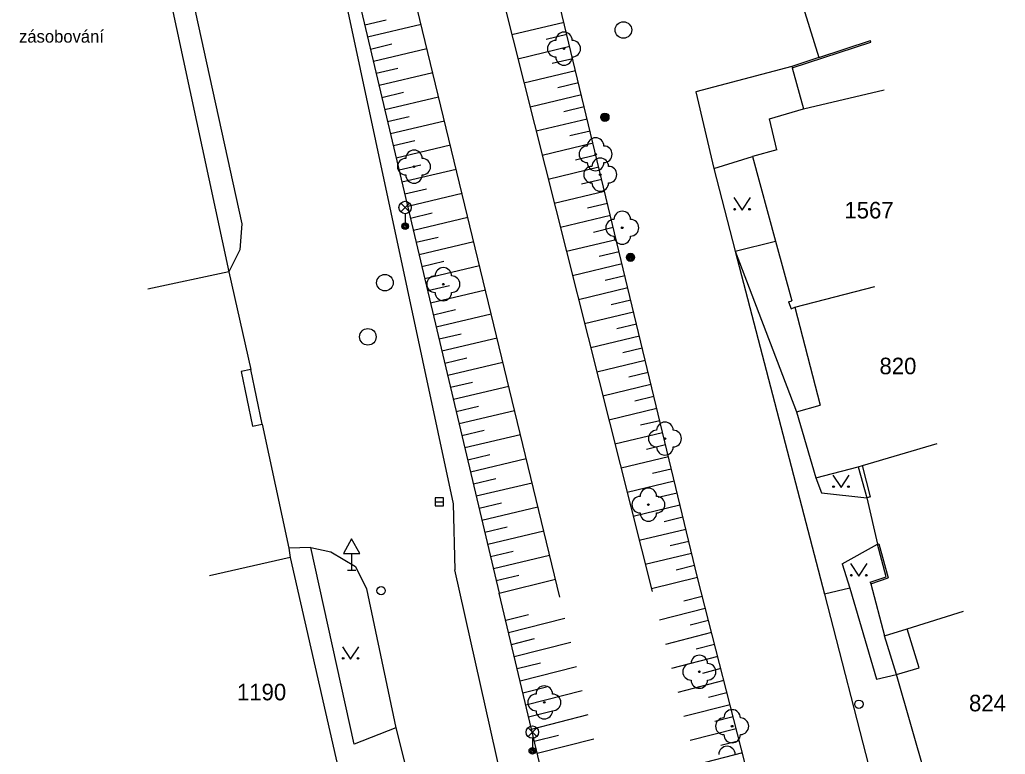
# Model space of a CAD drawing. Extents: x -539515 to -538098, y -1182060 to -1180157.
# Drawn here: x -539059.5 to -538999.9, y -1180485.6 to -1180441.2 of the extents above; entities that cross this region are included whole.
import ezdxf

# ---------------------------------------------------------------- set-up
doc = ezdxf.new("R2010")
doc.units = 0
for name, color, linetype in [('Vrstva 1', 7, 'Continuous'), ('Vrstva 11', 7, 'Continuous'), ('Vrstva 13', 7, 'Continuous'), ('Vrstva 22', 7, 'Continuous'), ('Vrstva 25', 7, 'Continuous'), ('Vrstva 27', 7, 'Continuous'), ('Vrstva 28', 7, 'Continuous'), ('Vrstva 29', 7, 'Continuous'), ('Vrstva 33', 7, 'Continuous'), ('Vrstva 34', 7, 'Continuous'), ('Vrstva 36', 7, 'Continuous'), ('Vrstva 41', 7, 'Continuous'), ('Vrstva 47', 7, 'Continuous'), ('Vrstva 68', 7, 'Continuous'), ('Vrstva 88', 7, 'Continuous')]:
    doc.layers.add(name, color=color, linetype=linetype)

msp = doc.modelspace()

# ---------------------------------------------------------------- linework, layer by layer
at = {"layer": 'Vrstva 1'}
for p, q in [((-539054.01, -1180422.97), (-539046.82, -1180456.41)), ((-539012.1, -1180446.56), (-539007.231, -1180445.422)), ((-539014.15, -1180447.16), (-539012.1, -1180446.56)), ((-539013.71, -1180449.05), (-539014.15, -1180447.16)), ((-539013.71, -1180449.05), (-539015.17, -1180449.45)), ((-539015.17, -1180449.45), (-539013.78, -1180454.57)), ((-539013.78, -1180454.57), (-539012.806, -1180458.156)), ((-539046.82, -1180456.41), (-539051.708, -1180457.461)), ((-539012.628, -1180458.547), (-539007.787, -1180457.297)), ((-539013, -1180458.219), (-539012.806, -1180458.156)), ((-539013, -1180458.219), (-539012.84, -1180458.641)), ((-539012.84, -1180458.641), (-539012.628, -1180458.547)), ((-539012.628, -1180458.547), (-539011.1, -1180464.461)), ((-539012.53, -1180464.87), (-539011.1, -1180464.461)), ((-539012.53, -1180464.87), (-539011.36, -1180468.859)), ((-539008.53, -1180468.108), (-539004.03, -1180466.781)), ((-539011.36, -1180468.859), (-539008.8, -1180468.19)), ((-539008.8, -1180468.19), (-539008.53, -1180468.108)), ((-539043.11, -1180473.68), (-539047.988, -1180474.773)), ((-539043.11, -1180473.68), (-539039.78, -1180488.31)), ((-539005.837, -1180477.983), (-539002.425, -1180476.922)), ((-539007.2, -1180478.41), (-539005.837, -1180477.983)), ((-539006.48, -1180480.75), (-539007.2, -1180478.41)), ((-539005.103, -1180480.344), (-539005.837, -1180477.983)), ((-539006.48, -1180480.75), (-539005.103, -1180480.344)), ((-539004.67, -1180487.07), (-539006.48, -1180480.75))]:
    msp.add_line(p, q, dxfattribs=at)
at = {"layer": 'Vrstva 11'}
for p, q in [((-539012.32, -1180439.742), (-539011.18, -1180443.461)), ((-539008.28, -1180470.07), (-539007.62, -1180472.87))]:
    msp.add_line(p, q, dxfattribs=at)
for points in [[(-539012.8, -1180444), (-539012.776, -1180444.087), (-539012.1, -1180446.56)], [(-539008.06, -1180475.17), (-539008.034, -1180475.269), (-539007.2, -1180478.41)]]:
    msp.add_lwpolyline(points, dxfattribs=at)
at = {"layer": 'Vrstva 13'}
for p, q in [((-539017.52, -1180450.16), (-539015.17, -1180449.45)), ((-539016.23, -1180455.17), (-539013.78, -1180454.57)), ((-539016.23, -1180455.17), (-539012.53, -1180464.87)), ((-539011.36, -1180468.859), (-539011.02, -1180469.77)), ((-539011.02, -1180469.77), (-539008.28, -1180470.07)), ((-539039.24, -1180484.95), (-539041.87, -1180473.08)), ((-539009.76, -1180474.06), (-539007.62, -1180472.87)), ((-539009.76, -1180474.06), (-539009.29, -1180475.53)), ((-539009.29, -1180475.53), (-539010.82, -1180475.89)), ((-539009.29, -1180475.53), (-539007.69, -1180481.03)), ((-539007.69, -1180481.03), (-539006.48, -1180480.75)), ((-539036.73, -1180483.96), (-539039.24, -1180484.95))]:
    msp.add_line(p, q, dxfattribs=at)
at = {"layer": 'Vrstva 22'}
for centre in [(-539026.57, -1180442.93), (-539024.66, -1180449.31), (-539035.63, -1180450.06), (-539024.38, -1180450.539), (-539023.05, -1180453.75), (-539033.86, -1180457.16), (-539020.47, -1180466.49), (-539021.47, -1180470.48), (-539018.39, -1180480.58), (-539027.76, -1180482.43), (-539016.41, -1180483.87)]:
    msp.add_circle(centre, 0.05, dxfattribs=at)
for centre, start, end in [((-539026.57, -1180442.43), 0, 180), ((-539027.07, -1180442.93), 90, 270), ((-539026.07, -1180442.93), 270, 90), ((-539026.57, -1180443.43), 180, 0), ((-539024.66, -1180448.81), 0, 180), ((-539035.63, -1180449.56), 0, 180), ((-539025.16, -1180449.31), 90, 270), ((-539024.16, -1180449.31), 270, 90), ((-539036.13, -1180450.06), 90, 270), ((-539035.13, -1180450.06), 270, 90), ((-539024.66, -1180449.81), 180, 0), ((-539024.38, -1180450.039), 0, 180), ((-539024.88, -1180450.539), 90, 270), ((-539023.88, -1180450.539), 270, 90), ((-539035.63, -1180450.56), 180, 0), ((-539024.38, -1180451.039), 180, 0), ((-539023.05, -1180453.25), 0, 180), ((-539023.55, -1180453.75), 90, 270), ((-539022.55, -1180453.75), 270, 90), ((-539023.05, -1180454.25), 180, 0), ((-539033.86, -1180456.66), 0, 180), ((-539034.36, -1180457.16), 90, 270), ((-539033.36, -1180457.16), 270, 90), ((-539033.86, -1180457.66), 180, 0), ((-539020.97, -1180466.49), 90, 270), ((-539020.47, -1180465.99), 0, 180), ((-539019.97, -1180466.49), 270, 90), ((-539020.47, -1180466.99), 180, 0), ((-539021.47, -1180469.98), 0, 180), ((-539021.97, -1180470.48), 90, 270), ((-539020.97, -1180470.48), 270, 90), ((-539021.47, -1180470.98), 180, 0), ((-539018.39, -1180480.08), 0, 180), ((-539018.89, -1180480.58), 90, 270), ((-539017.89, -1180480.58), 270, 90), ((-539027.76, -1180481.93), 0, 180), ((-539018.39, -1180481.08), 180, 0), ((-539028.26, -1180482.43), 90, 270), ((-539027.26, -1180482.43), 270, 90), ((-539027.76, -1180482.93), 180, 0), ((-539016.41, -1180483.37), 0, 180), ((-539016.91, -1180483.87), 90, 270), ((-539015.91, -1180483.87), 270, 90), ((-539016.41, -1180484.37), 180, 0), ((-539016.72, -1180485.58), 0, 180)]:
    msp.add_arc(centre, 0.5, start, end, dxfattribs=at)
at = {"layer": 'Vrstva 25'}
for centre, radius in [((-539024.1, -1180447.07), 0.25), ((-539024.1, -1180447.07), 0.2), ((-539024.1, -1180447.07), 0.15), ((-539024.1, -1180447.07), 0.1), ((-539024.1, -1180447.07), 0.05), ((-539022.55, -1180455.539), 0.25), ((-539022.55, -1180455.539), 0.2), ((-539022.55, -1180455.539), 0.15), ((-539022.55, -1180455.539), 0.1), ((-539022.55, -1180455.539), 0.05)]:
    msp.add_circle(centre, radius, dxfattribs=at)
at = {"layer": 'Vrstva 27'}
for p, q in [((-539038.606, -1180441.491), (-539037.314, -1180441.185)), ((-539038.433, -1180442.22), (-539035.201, -1180441.456)), ((-539026.568, -1180441.345), (-539029.719, -1180442.102)), ((-539026.392, -1180442.074), (-539027.65, -1180442.376)), ((-539038.26, -1180442.95), (-539036.966, -1180442.644)), ((-539038.087, -1180443.68), (-539034.848, -1180442.913)), ((-539026.217, -1180442.804), (-539029.352, -1180443.557)), ((-539026.042, -1180443.533), (-539027.293, -1180443.833)), ((-539037.915, -1180444.41), (-539036.617, -1180444.103)), ((-539037.742, -1180445.14), (-539034.495, -1180444.372)), ((-539025.867, -1180444.262), (-539028.986, -1180445.012)), ((-539025.692, -1180444.991), (-539026.936, -1180445.29)), ((-539037.569, -1180445.87), (-539036.269, -1180445.562)), ((-539025.517, -1180445.721), (-539028.62, -1180446.466)), ((-539037.397, -1180446.599), (-539034.142, -1180445.829)), ((-539025.341, -1180446.45), (-539026.579, -1180446.747)), ((-539037.224, -1180447.329), (-539035.92, -1180447.021)), ((-539037.051, -1180448.059), (-539033.789, -1180447.287)), ((-539025.166, -1180447.179), (-539028.253, -1180447.921)), ((-539024.991, -1180447.908), (-539026.223, -1180448.204)), ((-539036.879, -1180448.789), (-539035.572, -1180448.48)), ((-539036.706, -1180449.519), (-539033.436, -1180448.745)), ((-539024.816, -1180448.638), (-539027.887, -1180449.375)), ((-539036.533, -1180450.249), (-539035.224, -1180449.939)), ((-539024.641, -1180449.367), (-539025.866, -1180449.661)), ((-539036.36, -1180450.979), (-539033.083, -1180450.203)), ((-539024.466, -1180450.096), (-539027.52, -1180450.83)), ((-539024.29, -1180450.825), (-539025.509, -1180451.118)), ((-539036.188, -1180451.708), (-539034.875, -1180451.398)), ((-539036.015, -1180452.438), (-539032.73, -1180451.661)), ((-539024.115, -1180451.555), (-539027.154, -1180452.284)), ((-539023.94, -1180452.284), (-539025.152, -1180452.575)), ((-539035.842, -1180453.168), (-539034.527, -1180452.857)), ((-539035.67, -1180453.898), (-539032.377, -1180453.119)), ((-539023.765, -1180453.013), (-539026.787, -1180453.739)), ((-539023.59, -1180453.743), (-539024.795, -1180454.032)), ((-539035.497, -1180454.628), (-539034.178, -1180454.316)), ((-539035.324, -1180455.358), (-539032.024, -1180454.577)), ((-539023.415, -1180454.472), (-539026.421, -1180455.194)), ((-539023.239, -1180455.201), (-539024.439, -1180455.489)), ((-539035.151, -1180456.087), (-539033.83, -1180455.775)), ((-539034.979, -1180456.817), (-539031.671, -1180456.035)), ((-539023.064, -1180455.93), (-539026.054, -1180456.649)), ((-539022.889, -1180456.66), (-539024.082, -1180456.946)), ((-539034.806, -1180457.547), (-539033.481, -1180457.234)), ((-539034.633, -1180458.277), (-539031.318, -1180457.492)), ((-539022.714, -1180457.389), (-539025.688, -1180458.103)), ((-539022.539, -1180458.118), (-539023.725, -1180458.403)), ((-539034.461, -1180459.007), (-539033.133, -1180458.693)), ((-539022.364, -1180458.847), (-539025.321, -1180459.558)), ((-539034.288, -1180459.737), (-539030.965, -1180458.95)), ((-539022.188, -1180459.577), (-539023.368, -1180459.86)), ((-539034.115, -1180460.467), (-539032.784, -1180460.152)), ((-539033.942, -1180461.196), (-539030.612, -1180460.408)), ((-539022.013, -1180460.306), (-539024.955, -1180461.012)), ((-539021.838, -1180461.035), (-539023.012, -1180461.317)), ((-539033.77, -1180461.926), (-539032.436, -1180461.611)), ((-539021.663, -1180461.764), (-539024.588, -1180462.467)), ((-539033.597, -1180462.656), (-539030.259, -1180461.866)), ((-539021.488, -1180462.494), (-539022.655, -1180462.774)), ((-539033.424, -1180463.386), (-539032.088, -1180463.07)), ((-539033.252, -1180464.116), (-539029.906, -1180463.324)), ((-539021.313, -1180463.223), (-539024.222, -1180463.921)), ((-539021.137, -1180463.952), (-539022.298, -1180464.231)), ((-539033.079, -1180464.846), (-539031.739, -1180464.528)), ((-539032.906, -1180465.575), (-539029.553, -1180464.782)), ((-539020.962, -1180464.681), (-539023.856, -1180465.376)), ((-539020.787, -1180465.411), (-539021.941, -1180465.688)), ((-539032.733, -1180466.305), (-539031.391, -1180465.988)), ((-539032.561, -1180467.035), (-539029.2, -1180466.24)), ((-539020.612, -1180466.14), (-539023.489, -1180466.831)), ((-539020.437, -1180466.869), (-539021.584, -1180467.145)), ((-539032.388, -1180467.765), (-539031.042, -1180467.447)), ((-539032.215, -1180468.495), (-539028.847, -1180467.698)), ((-539020.262, -1180467.598), (-539023.123, -1180468.286)), ((-539020.086, -1180468.328), (-539021.228, -1180468.602)), ((-539032.043, -1180469.225), (-539030.694, -1180468.905)), ((-539031.87, -1180469.954), (-539028.494, -1180469.156)), ((-539019.911, -1180469.057), (-539022.756, -1180469.74)), ((-539019.736, -1180469.786), (-539020.871, -1180470.059)), ((-539034.35, -1180470.31), (-539033.85, -1180470.31)), ((-539031.697, -1180470.684), (-539030.345, -1180470.364)), ((-539031.524, -1180471.414), (-539028.141, -1180470.613)), ((-539019.561, -1180470.515), (-539022.39, -1180471.195)), ((-539019.386, -1180471.245), (-539020.514, -1180471.516)), ((-539031.352, -1180472.144), (-539029.997, -1180471.823)), ((-539019.211, -1180471.974), (-539022.023, -1180472.65)), ((-539031.179, -1180472.874), (-539027.788, -1180472.072)), ((-539019.035, -1180472.703), (-539020.157, -1180472.973)), ((-539031.006, -1180473.604), (-539029.648, -1180473.282)), ((-539030.834, -1180474.334), (-539027.435, -1180473.529)), ((-539018.86, -1180473.432), (-539021.657, -1180474.104)), ((-539018.685, -1180474.162), (-539019.801, -1180474.43)), ((-539030.661, -1180475.063), (-539029.3, -1180474.741)), ((-539018.51, -1180474.891), (-539021.29, -1180475.559)), ((-539030.48, -1180475.83), (-539027.082, -1180474.987)), ((-539018.217, -1180476.031), (-539019.326, -1180476.316)), ((-539030.092, -1180477.47), (-539028.716, -1180477.121)), ((-539029.919, -1180478.2), (-539026.515, -1180477.337)), ((-539018.03, -1180476.757), (-539020.804, -1180477.471)), ((-539017.843, -1180477.484), (-539018.953, -1180477.769)), ((-539017.656, -1180478.21), (-539020.434, -1180478.925)), ((-539029.746, -1180478.929), (-539028.354, -1180478.577)), ((-539029.573, -1180479.659), (-539026.165, -1180478.795)), ((-539017.469, -1180478.936), (-539018.581, -1180479.223)), ((-539017.282, -1180479.663), (-539020.064, -1180480.378)), ((-539029.4, -1180480.389), (-539027.993, -1180480.032)), ((-539029.227, -1180481.119), (-539025.814, -1180480.254)), ((-539017.095, -1180480.389), (-539018.208, -1180480.676)), ((-539029.054, -1180481.849), (-539027.631, -1180481.488)), ((-539016.908, -1180481.115), (-539019.694, -1180481.832)), ((-539028.881, -1180482.579), (-539025.463, -1180481.712)), ((-539016.721, -1180481.842), (-539017.836, -1180482.129)), ((-539016.534, -1180482.568), (-539019.323, -1180483.286)), ((-539028.709, -1180483.309), (-539027.269, -1180482.944)), ((-539028.536, -1180484.039), (-539025.112, -1180483.171)), ((-539016.347, -1180483.294), (-539017.464, -1180483.582)), ((-539028.363, -1180484.769), (-539026.908, -1180484.4)), ((-539016.16, -1180484.021), (-539018.953, -1180484.739)), ((-539028.19, -1180485.499), (-539024.762, -1180484.629)), ((-539015.973, -1180484.747), (-539017.091, -1180485.035)), ((-539015.787, -1180485.473), (-539018.583, -1180486.193))]:
    msp.add_line(p, q, dxfattribs=at)
msp.add_lwpolyline([(-539034.35, -1180470.56), (-539033.85, -1180470.56), (-539033.85, -1180470.06), (-539034.35, -1180470.06)], close=True, dxfattribs=at)
for centre in [(-539022.98, -1180441.8), (-539037.39, -1180457.07), (-539038.42, -1180460.34)]:
    msp.add_circle(centre, 0.5, dxfattribs=at)
at = {"layer": 'Vrstva 28'}
for centre in [(-539037.62, -1180475.68), (-539008.75, -1180482.539)]:
    msp.add_circle(centre, 0.25, dxfattribs=at)
at = {"layer": 'Vrstva 29'}
for p, q in [((-539032.443, -1180431.289), (-539021.25, -1180475.719)), ((-539026.82, -1180476.07), (-539037.301, -1180432.781)), ((-539018.51, -1180474.89), (-539028.45, -1180433.51)), ((-539040.16, -1180434.92), (-539030.48, -1180475.83)), ((-539012.048, -1180500), (-539018.51, -1180474.89)), ((-539026.11, -1180494.28), (-539030.48, -1180475.83))]:
    msp.add_line(p, q, dxfattribs=at)
at = {"layer": 'Vrstva 33'}
for p, q in [((-539036.434, -1180452.791), (-539035.906, -1180452.261)), ((-539036.434, -1180452.261), (-539035.906, -1180452.791)), ((-539036.17, -1180452.9), (-539036.17, -1180453.65)), ((-539028.744, -1180484.491), (-539028.216, -1180483.961)), ((-539028.744, -1180483.961), (-539028.216, -1180484.491)), ((-539028.48, -1180484.6), (-539028.48, -1180485.35))]:
    msp.add_line(p, q, dxfattribs=at)
for centre, radius in [((-539036.17, -1180452.526), 0.375), ((-539036.17, -1180453.651), 0.2), ((-539036.17, -1180453.651), 0.145), ((-539036.17, -1180453.651), 0.0876), ((-539028.48, -1180484.226), 0.375), ((-539028.48, -1180485.351), 0.2), ((-539028.48, -1180485.351), 0.145), ((-539028.48, -1180485.351), 0.0876)]:
    msp.add_circle(centre, radius, dxfattribs=at)
at = {"layer": 'Vrstva 34'}
for p, q in [((-539039.4, -1180473.424), (-539039.4, -1180474.44)), ((-539039.65, -1180474.44), (-539039.15, -1180474.44))]:
    msp.add_line(p, q, dxfattribs=at)
msp.add_lwpolyline([(-539039.9, -1180473.424), (-539038.9, -1180473.424), (-539039.4, -1180472.556)], close=True, dxfattribs=at)
at = {"layer": 'Vrstva 36'}
for points in [[(-539016.308, -1180451.93), (-539015.808, -1180452.68), (-539015.308, -1180451.93)], [(-539010.331, -1180468.695), (-539009.831, -1180469.445), (-539009.331, -1180468.695)], [(-539009.253, -1180474.047), (-539008.753, -1180474.797), (-539008.253, -1180474.047)], [(-539039.962, -1180479.07), (-539039.462, -1180479.82), (-539038.962, -1180479.07)]]:
    msp.add_lwpolyline(points, dxfattribs=at)
for centre in [(-539016.258, -1180452.63), (-539015.359, -1180452.63), (-539010.281, -1180469.395), (-539009.382, -1180469.395), (-539009.203, -1180474.747), (-539008.304, -1180474.747), (-539039.912, -1180479.77), (-539039.013, -1180479.77)]:
    msp.add_circle(centre, 0.05, dxfattribs=at)
at = {"layer": 'Vrstva 68'}
for p, q in [((-539011.18, -1180443.461), (-539008.05, -1180442.438)), ((-539011.18, -1180443.461), (-539012.8, -1180444)), ((-539045.49, -1180462.32), (-539046.079, -1180462.445)), ((-539046.079, -1180462.445), (-539045.399, -1180465.734)), ((-539044.81, -1180465.609), (-539045.49, -1180462.32)), ((-539045.399, -1180465.734), (-539044.81, -1180465.609)), ((-539008.8, -1180468.19), (-539008.28, -1180470.07)), ((-539008.053, -1180470.016), (-539008.53, -1180468.108)), ((-539008.053, -1180470.016), (-539008.28, -1180470.07)), ((-539007.62, -1180472.87), (-539007.552, -1180472.852)), ((-539007.11, -1180474.84), (-539007.62, -1180472.87)), ((-539007.552, -1180472.852), (-539006.99, -1180474.906)), ((-539008.06, -1180475.17), (-539007.11, -1180474.84)), ((-539008.034, -1180475.269), (-539006.99, -1180474.906))]:
    msp.add_line(p, q, dxfattribs=at)
msp.add_lwpolyline([(-539012.776, -1180444.087), (-539008.02, -1180442.531), (-539008.05, -1180442.438)], dxfattribs=at)
at = {"layer": 'Vrstva 88'}
for p, q in [((-539052.959, -1180421.847), (-539046.04, -1180453.51)), ((-539040.64, -1180435.98), (-539033.26, -1180470.44)), ((-539012.8, -1180444), (-539018.6, -1180445.531)), ((-539018.6, -1180445.53), (-539017.52, -1180450.16)), ((-539017.52, -1180450.16), (-539016.23, -1180455.17)), ((-539046.04, -1180453.51), (-539046.15, -1180455.08)), ((-539046.15, -1180455.08), (-539046.82, -1180456.41)), ((-539016.23, -1180455.17), (-539010.82, -1180475.89)), ((-539046.82, -1180456.41), (-539045.49, -1180462.32)), ((-539044.81, -1180465.61), (-539043.19, -1180473.11)), ((-539033.26, -1180470.44), (-539033.17, -1180474.42)), ((-539041.87, -1180473.08), (-539043.19, -1180473.11)), ((-539043.19, -1180473.11), (-539043.11, -1180473.68)), ((-539041.87, -1180473.08), (-539040.66, -1180473.34)), ((-539040.66, -1180473.34), (-539039.16, -1180474.21)), ((-539039.16, -1180474.21), (-539038.51, -1180475.57)), ((-539028.56, -1180494.92), (-539033.17, -1180474.42)), ((-539038.51, -1180475.57), (-539036.73, -1180483.96)), ((-539010.82, -1180475.89), (-539007.75, -1180487.88)), ((-539036.73, -1180483.96), (-539035.73, -1180487.9))]:
    msp.add_line(p, q, dxfattribs=at)

# ---------------------------------------------------------------- texts
at = {"layer": 'Vrstva 41'}
msp.add_text('zásobování', height=0.75, dxfattribs=at).set_placement((-539059.497, -1180442.563))
at = {"layer": 'Vrstva 47'}
for s, p in [('1567', (-539009.626, -1180453.188)), ('820', (-539007.507, -1180462.602)), ('1190', (-539046.329, -1180482.305)), ('824', (-539002.097, -1180482.969))]:
    msp.add_text(s, height=1, dxfattribs=at).set_placement(p)

doc.saveas('drawing.dxf')
